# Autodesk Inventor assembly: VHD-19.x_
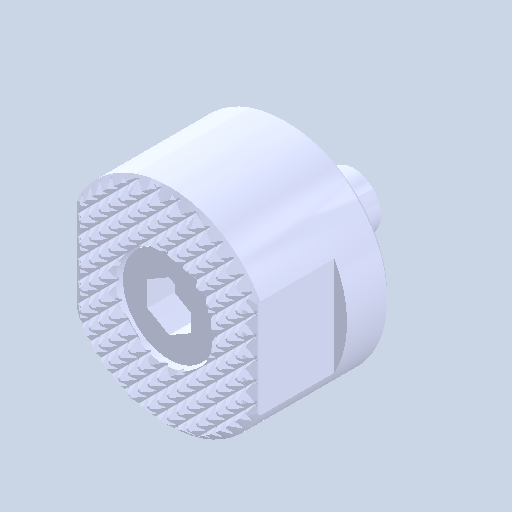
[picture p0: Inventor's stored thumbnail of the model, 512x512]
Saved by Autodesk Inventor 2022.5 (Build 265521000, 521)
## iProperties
Created: 2024-05
Part Number: VHD-19.x_
Document SubType Name: Assembly
Designer: ImaoCorp
Author: ImaoCorp
Sending System: SOLIDWORKS 2022-2022290
MC: AMD64
MC_MODEL: Intel64 Family 6 Model 60 Stepping 3, GenuineIntel
OS: Windows_NT
FRU: Parasolid Version 33.1, build 260,  4-25-2022
FORMAT: text
GUISE: transmit
KEY: FILEVHD-19.x_t
DATE: Mon May 20 16:28:28 2024
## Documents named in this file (3)
- X:\14_SW2022-Inv2022\保留中\mitee-bite\データ\vhd-19\VHD-19.x_.iam
- X:\14_SW2022-Inv2022\保留中\mitee-bite\データ\vhd-19\VHD-19_01.ipt
- X:\14_SW2022-Inv2022\保留中\mitee-bite\データ\vhd-19\VHD-19_02.ipt
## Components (2 placed, 2 different names)
1. VHD-19_01
2. VHD-19_02
